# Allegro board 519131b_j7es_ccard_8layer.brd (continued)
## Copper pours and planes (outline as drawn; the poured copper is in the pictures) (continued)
N31223527 on TOP: 106.43,132.96 104.27,132.96 104.01,133.21 104.01,136.39 102.62,136.39 102.36,136.64 102.36,137.15 102.62,137.4 104.01,137.4 104.01,139.31 106.43,139.31
N31823861 on TOP: 154.94,30.22 149.22,30.22 149.22,31.49 152.91,31.49 153.29,31.1 154.81,31.1 154.94,30.98

Small or netless copper shapes (teardrops, artwork), in the pictures only: 2 on TOP, 2 on BOTTOM

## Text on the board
BOTTOM: LOGIC 519132 REV A | PWB 519131 REV A | LAYER 8
Ref Des/Assembly Bottom: B | H | C | A | E | G | F | BOTTOM ASSEMBLY | J721EX SOM 941x PMIC BOTTOM ASSEMBLY REV.E5
Board Geometry/Soldermask Bottom: SMS
Ref Des/Silkscreen Bottom: SD CARD | GND | WIFI | 1 | NOT FCC APPROVED FOR RESALE | FOR EVALUATION ONLY; | ASSY 519130 REV | S/N | A2B | A | B | TIDEP-01020 | BSLK
User.Comments: CR_PMIC_2 | TIDEP-01020
TOP: LAYER 1
Ref Des/Assembly Top: TOP ASSEMBLY | J721EX SOM 941x PMIC TOP ASSEMBLY REV.E5
Board Geometry/Soldermask Top: SMC
Ref Des/Silkscreen Top: MCU_RESETZ | WAKE | FAN | CAM4 | CAM3 | CAM2 | CAM1 | FPD-LINK VIDEO | 1 | COMM | MIC[4:3] | MIC[6:5] | MIC[2:1] | GND | BOOTMODE | MCU_PORZ | A | SOC_PORZ | DEBUG | CAN_WKUP | SPKR[4:1] | VSYS_16V0 | P | N | VBAT_SYS | CONSOLE | CHIMES | B3B/FMB/AM | B3A/FMA | RESET_REQZ | GNSS | USB1 | DISPLAY | USBO | VBAT | PG_LM5175 | PVDD | PG_LM5141 | CAN-WAKE | J7ES CCARD | + | - | TIDEP-01020 | TSLK
L2-SIGNAL: LAYER 2
L3-GND: LAYER 3
L4-SIGNAL: LAYER 4
L5-SIGNAL: LAYER 5
L6-PWR: LAYER 6
L7-SIGNAL: LAYER 7
XSECTION_CHART: 10 | BACKDRILLING TO BE DONE FROM L8 TO L04. | *  SURFACE - AIR 0 MIL | *  DIELECTRIC - SOLDER_MASK 1 MIL | L1: TOP PLANE - COPPER 2 MIL | *  DIELECTRIC - FR-4 4.9 MIL | L2: L2-SIGNAL CONDUCTOR - COPPER 0.6 MIL | *  DIELECTRIC - FR-4 4 MIL | L3: L3-GND PLANE - COPPER 1.2 MIL | *  DIELECTRIC - FR-4 4.5 MIL | L4: L4-SIGNAL CONDUCTOR - COPPER 0.6 MIL | *  DIELECTRIC - FR-4 25 MIL | L5: L5-SIGNAL CONDUCTOR - COPPER 0.6 MIL | L6: L6-PWR PLANE - COPPER 1.2 MIL | L7: L7-SIGNAL CONDUCTOR - COPPER 0.6 MIL | L8: BOTTOM PLANE - COPPER 2 MIL | DESIGN CROSS SECTION CHART | ___________________________ | TOTAL THICKNESS 62.6 MIL
USER_PART_NUM_BOTTOM: BSLKC
USER_PART_NUM_TOP: TSLKC
DISPLAY_TOP: 2 | SPC
DISPLAY_BOTTOM: IS INTENTIONAL | SHORT ACCROSS PL1 ON TOP LAYER | SPS
DIMENSION: 10
User.9: 4.  SOLDERMASK ON BOTH SIDES OF THE BOARD SHALL BE S.M.O.B.C., LPI, COLOR GREEN. | 3.  MINIMUM CLEARANCE ON THE BOARD SHALL BE 3.0 MILS. | 5.  PLATED THRU HOLE SIZE TOLERANCES SHALL BE +/- .003 INCH. | 9.  IMPEDANCE CONTROL: | 1.  TOTAL BOARD THICKNESS SHALL BE .062 +/- 10% INCHES. | 2.  REFER TO STACKUP DRAWING FOR COPPER WEIGHT. | 6.  DRC'S MUST BE RUN ON THE GERBERS BEFORE BUILDING BOARDS UNLESS PRIOR | 8.  ENVIRONMENTAL COMPLIANCE: | NOTES: UNLESS OTHERWISE SPECIFIED | 7.  FINISHED BOARD SHALL BE FREE OF BURRS ON EDGES. | REFER TO STACKUP DRAWING FOR IMPEDANCE CONTROL. | LEAD (PB)-FREE, ROHS, AND REACH COMPLIANT WITHOUT EXEMPTIONS. | AVERAGE COPPER ON THE WALL OF THE | ALL MATERIAL SHALL BE NEMA GRADE FR-4 OR EQUIVALENT. (Tg>=170 DEG. C) | FLAMMABILITY, 94V-0. | PLATED HOLE SHALL BE PER IPC CLASS 2. | UNPLATED THRU HOLE SIZE TOLERANCES SHALL BE +/- .002 INCH. | MINIMUM TRACE WIDTH ON THE BOARD SHALL BE 3.0 MILS. | APPROVAL IS GIVEN IN WRITING. | TO BE NON-CONDUCTIVE VIA FILLED. | ALL VIAS,7.99, 8, 10 AND 12 MIL | NOTES: | - DRILL SIZES LISTED IN LEGEND | ARE CONSIDERED FINISHED. | - VENDOR IS REQUIRED TO SELECT | TOOLING FOR OVERDRILLING. | - LEGEND DOES NOT SPECIFY DEPTH | INTO ADJACENT DIELECTRIC LAYER. | FIGURE | SIZE | 7.99 | BACKDRILL: BOTTOM to L4 | ALL UNITS ARE IN MILS | TOLERANCE | +3.0/-3.0 | PLATED | QTY | 16 | START | L8 | TARGET | L4 | MUST CUT | L5 | MUST NOT CUT | L3 | DATE | DESIGN ENGR | PROJECT ENGR | ENGR MGR | NEXT ASSEMBLY | APPROVED | CHECKED | DRAFTING | ENGR | NONE | 1 OF 1
User.14: FIGURE | SIZE | 7.99 | 8.0 | 10.0 | 12.0 | 13.0 | 25.0 | 28.0 | 35.0 | 38.0 | 39.0 | 40.0 | 43.0 | 51.0 | 51.18 | 58.0 | 60.0 | 63.0 | 91.0 | 98.0 | 100.0 | 125.0 | 47.24 | 70.0x26.0 | 90.0x26.0 | 158.0x78.0 | PLATED | NON-PLATED | DRILL CHART | ALL UNITS ARE IN MILS | QTY | 16 | 21 | 1896 | 104 | 19 | 2174 | 22 | 95 | 31 | 3 | 18 | 4 | 2 | 12 | 10 | 8 | 7 | 1 | 28 | 6 | TOL | NOTE
